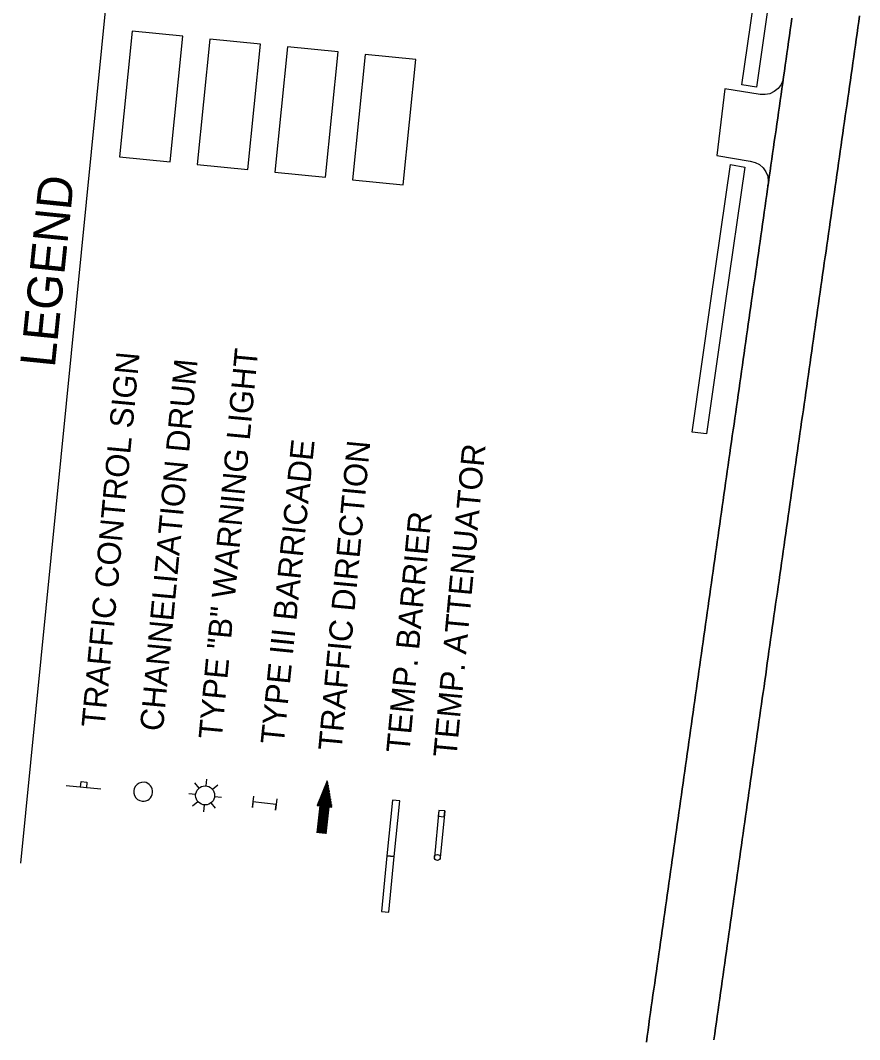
# Model space of a CAD drawing. Extents: x 1795987 to 1799700, y 243690 to 251545.
# Drawn here: x 1797261.2 to 1797542.5, y 247111.4 to 247453.1 of the extents above; entities that cross this region are included whole.
import ezdxf

# ---------------------------------------------------------------- set-up
doc = ezdxf.new("R2010")
doc.units = 0
for name, color, linetype in [('EP', 7, 'Continuous'), ('LEGEND', 7, 'Continuous'), ('Level 23', 7, 'Continuous'), ('Level 62', 7, 'Continuous')]:
    doc.layers.add(name, color=color, linetype=linetype)

# ---------------------------------------------------------------- blocks, each defined once
blk = doc.blocks.new('T21LR')
at = {"layer": 'Level 23'}
for p, q in [((0, 2), (31.5, 2)), ((0, -2), (31.5, -2))]:
    blk.add_line(p, q, dxfattribs=at)
blk.add_lwpolyline([(0, -2), (4, -2), (4, 2), (0, 2)], close=True, dxfattribs=at)
blk.add_circle((31.5, 0), 2, dxfattribs=at)

msp = doc.modelspace()

# ---------------------------------------------------------------- linework, layer by layer
at = {"layer": 'EP'}
for p, q in [((1797507.92, 247430.67), (1797502.98, 247431.42)), ((1797499.19, 247404.72), (1797504.07, 247403.85)), ((1797491.2, 247314.5), (1797486.32, 247315.04))]:
    msp.add_line(p, q, dxfattribs=at)
for points in [[(1797502.98, 247431.42), (1797509.89, 247479.28), (1797512.41, 247496.92), (1797513.21, 247499.92), (1797514.39, 247502.79), (1797515.55, 247504.9), (1797517.77, 247509.13), (1797519.86, 247513.31), (1797520.78, 247515.42), (1797521.93, 247518.67), (1797522.28, 247519.96), (1797522.83, 247522.6), (1797523.1, 247524.61), (1797523.26, 247527.63), (1797523.1, 247531.02), (1797522.82, 247533.27), (1797521.91, 247537.81), (1797521.35, 247540.15), (1797520.54, 247543.7), (1797520.12, 247547.31), (1797520.09, 247550.71), (1797523.74, 247576.05), (1797530.2, 247621.54), (1797536.99, 247668.47)], [(1797541.84, 247667.67), (1797535.11, 247620.83), (1797528.62, 247575.39), (1797524.96, 247549.93), (1797525.06, 247548.02), (1797525.55, 247543.91), (1797526.45, 247539.86), (1797526.65, 247538.96), (1797527.41, 247535.59), (1797527.98, 247531.38), (1797528.16, 247527.13), (1797526.97, 247518.48), (1797526.28, 247516.25), (1797524.64, 247511.95), (1797522.63, 247507.8), (1797522.17, 247506.93), (1797521.53, 247505.59), (1797517.43, 247496.48), (1797514.72, 247478.52), (1797507.92, 247430.67)], [(1797486.32, 247315.04), (1797492.66, 247359.05), (1797499.19, 247404.72)], [(1797504.07, 247403.85), (1797497.45, 247358.32), (1797491.2, 247314.5)]]:
    msp.add_lwpolyline(points, dxfattribs=at)
at = {"layer": 'LEGEND'}
for p, q in [((1797261.35, 247170.53), (1797308.29, 247644.28)), ((1797288.14, 247195.31), (1797276.49, 247196.46)), ((1797321.07, 247195.7), (1797319.61, 247197.49)), ((1797323.41, 247196.41), (1797323.64, 247198.71)), ((1797327.36, 247196.72), (1797325.57, 247195.26)), ((1797364.05, 247198.17), (1797360.6, 247189.86)), ((1797365.57, 247189.3), (1797364.05, 247198.17)), ((1797319.92, 247193.55), (1797317.62, 247193.78)), ((1797326.28, 247192.92), (1797328.58, 247192.69)), ((1797318.84, 247189.74), (1797320.63, 247191.21)), ((1797322.78, 247190.06), (1797322.55, 247187.76)), ((1797326.59, 247188.98), (1797325.12, 247190.76)), ((1797361.53, 247189.75), (1797360.52, 247180.73)), ((1797360.6, 247189.86), (1797361.53, 247189.75)), ((1797363.62, 247180.38), (1797364.63, 247189.4)), ((1797364.63, 247189.4), (1797365.57, 247189.3))]:
    msp.add_line(p, q, dxfattribs=at)
for points in [[(1797311.42, 247405.67), (1797315.58, 247447.74), (1797298.6, 247449.42), (1797294.43, 247407.35)], [(1797337.45, 247403.09), (1797341.62, 247445.16), (1797324.63, 247446.84), (1797320.46, 247404.77)], [(1797363.49, 247400.51), (1797367.66, 247442.58), (1797350.67, 247444.26), (1797346.5, 247402.19)], [(1797389.53, 247397.93), (1797393.69, 247440), (1797376.71, 247441.68), (1797372.54, 247399.61)], [(1797281.34, 247195.98), (1797281.54, 247197.92), (1797283.48, 247197.73), (1797283.28, 247195.79)], [(1797388.35, 247191.39), (1797385.87, 247191.64), (1797384.02, 247172.98), (1797386.51, 247172.73)], [(1797386.51, 247172.73), (1797384.02, 247172.98), (1797382.17, 247154.32), (1797384.66, 247154.07)]]:
    msp.add_lwpolyline(points, close=True, dxfattribs=at)
for points in [[(1797363.56, 247196.99), (1797361.71, 247180.59)], [(1797363.91, 247197.85), (1797361.97, 247180.56)], [(1797364.15, 247197.6), (1797362.23, 247180.53)], [(1797364.31, 247196.68), (1797362.49, 247180.5)], [(1797347.12, 247192.11), (1797346.67, 247188.24), (1797346.89, 247190.18), (1797339.14, 247191.08), (1797338.92, 247189.14), (1797339.37, 247193.01)], [(1797362.12, 247193.53), (1797360.68, 247180.71)], [(1797362.48, 247194.39), (1797360.94, 247180.68)], [(1797362.84, 247195.26), (1797361.2, 247180.65)], [(1797363.2, 247196.12), (1797361.45, 247180.62)], [(1797364.46, 247195.75), (1797362.75, 247180.48)], [(1797364.62, 247194.83), (1797363, 247180.45)], [(1797364.78, 247193.91), (1797363.26, 247180.42)], [(1797364.94, 247192.99), (1797363.52, 247180.39)], [(1797360.69, 247190.07), (1797360.66, 247189.85)], [(1797361.04, 247190.94), (1797360.92, 247189.82)], [(1797361.4, 247191.8), (1797361.18, 247189.79)], [(1797361.76, 247192.67), (1797361.44, 247189.76)], [(1797365.1, 247192.06), (1797364.79, 247189.38)], [(1797365.25, 247191.14), (1797365.05, 247189.35)], [(1797365.41, 247190.22), (1797365.31, 247189.33)]]:
    msp.add_lwpolyline(points, dxfattribs=at)
msp.add_circle((1797323.1, 247193.23), 3.19, dxfattribs=at)
for start, end in [(84.3414, 264.3414), (264.3414, 84.3414)]:
    msp.add_arc((1797302.33, 247194.48), 3.18, start, end, dxfattribs=at)
at = {"layer": 'Level 62'}
for points in [[(1797471, 247110.54), (1797471.28, 247112.51), (1797471.56, 247114.49), (1797471.84, 247116.46), (1797472.11, 247118.43), (1797472.39, 247120.41), (1797472.67, 247122.38), (1797472.95, 247124.35), (1797473.23, 247126.33), (1797473.51, 247128.3), (1797473.79, 247130.27), (1797474.07, 247132.25), (1797474.35, 247134.22), (1797474.63, 247136.19), (1797474.91, 247138.17), (1797475.19, 247140.14), (1797475.47, 247142.12), (1797475.75, 247144.09), (1797476.03, 247146.06), (1797476.31, 247148.04), (1797476.59, 247150.01), (1797476.87, 247151.98), (1797477.15, 247153.96), (1797477.42, 247155.93), (1797477.7, 247157.9), (1797477.98, 247159.88), (1797478.26, 247161.85), (1797478.54, 247163.83), (1797478.82, 247165.8), (1797479.1, 247167.77), (1797479.38, 247169.75), (1797479.66, 247171.72), (1797479.94, 247173.69), (1797480.22, 247175.67), (1797480.5, 247177.64), (1797480.78, 247179.61), (1797481.06, 247181.59), (1797481.34, 247183.56), (1797481.62, 247185.54), (1797481.9, 247187.51), (1797482.18, 247189.48), (1797482.46, 247191.46), (1797482.74, 247193.43), (1797483.01, 247195.4), (1797483.29, 247197.38), (1797483.57, 247199.35), (1797483.85, 247201.32), (1797484.13, 247203.3), (1797484.41, 247205.27), (1797484.69, 247207.25), (1797484.97, 247209.22), (1797485.25, 247211.19), (1797485.53, 247213.17), (1797485.81, 247215.14), (1797486.09, 247217.11), (1797486.37, 247219.09), (1797486.65, 247221.06), (1797486.93, 247223.03), (1797487.21, 247225.01), (1797487.49, 247226.98), (1797487.77, 247228.96), (1797488.05, 247230.93), (1797488.32, 247232.9), (1797488.6, 247234.88), (1797488.88, 247236.85), (1797489.16, 247238.82), (1797489.44, 247240.8), (1797489.72, 247242.77), (1797490, 247244.74), (1797490.28, 247246.72), (1797490.56, 247248.69), (1797490.84, 247250.67), (1797491.12, 247252.64), (1797491.4, 247254.61), (1797491.68, 247256.59), (1797491.96, 247258.56), (1797492.24, 247260.53), (1797492.52, 247262.51), (1797492.8, 247264.48), (1797493.08, 247266.45), (1797493.36, 247268.43), (1797493.63, 247270.4), (1797493.91, 247272.38), (1797494.19, 247274.35), (1797494.47, 247276.32), (1797494.76, 247278.3), (1797495.04, 247280.27), (1797495.32, 247282.24), (1797495.6, 247284.21), (1797495.88, 247286.19), (1797496.16, 247288.16), (1797496.44, 247290.13), (1797496.73, 247292.1), (1797497.01, 247294.08), (1797497.29, 247296.05), (1797497.57, 247298.02), (1797497.85, 247300), (1797498.13, 247301.97), (1797498.42, 247303.94), (1797498.7, 247305.91), (1797498.98, 247307.89), (1797499.26, 247309.86), (1797499.54, 247311.83), (1797499.82, 247313.8), (1797500.11, 247315.78), (1797500.39, 247317.75), (1797500.67, 247319.72), (1797500.95, 247321.7), (1797501.23, 247323.67), (1797501.51, 247325.64), (1797501.8, 247327.61), (1797502.08, 247329.59), (1797502.36, 247331.56), (1797502.64, 247333.53), (1797502.92, 247335.5), (1797503.2, 247337.48), (1797503.48, 247339.45), (1797503.77, 247341.42), (1797504.05, 247343.39), (1797504.33, 247345.37), (1797504.61, 247347.34), (1797504.89, 247349.31), (1797505.17, 247351.29), (1797505.46, 247353.26), (1797505.74, 247355.23), (1797506.02, 247357.2), (1797506.3, 247359.18), (1797506.58, 247361.15), (1797506.86, 247363.12), (1797507.15, 247365.09), (1797507.43, 247367.07), (1797507.71, 247369.04), (1797507.99, 247371.01), (1797508.27, 247372.99), (1797508.55, 247374.96), (1797508.84, 247376.93), (1797509.12, 247378.9), (1797509.4, 247380.88), (1797509.68, 247382.85), (1797509.96, 247384.82), (1797510.24, 247386.79), (1797510.52, 247388.77), (1797510.81, 247390.74), (1797511.09, 247392.71), (1797511.37, 247394.69), (1797511.65, 247396.66), (1797511.93, 247398.63), (1797512.21, 247400.6), (1797512.5, 247402.58), (1797512.78, 247404.55), (1797513.06, 247406.52), (1797513.34, 247408.49), (1797513.62, 247410.47), (1797513.9, 247412.44), (1797514.19, 247414.41), (1797514.47, 247416.39), (1797514.75, 247418.36), (1797515.03, 247420.33), (1797515.31, 247422.3), (1797515.59, 247424.28), (1797515.88, 247426.25), (1797516.16, 247428.22), (1797516.44, 247430.19), (1797516.72, 247432.17), (1797517, 247434.14), (1797517.28, 247436.11), (1797517.57, 247438.09), (1797517.85, 247440.06), (1797518.13, 247442.03), (1797518.41, 247444), (1797518.69, 247445.98), (1797518.97, 247447.95), (1797519.25, 247449.92), (1797519.54, 247451.89), (1797519.82, 247453.87)], [(1797519.82, 247453.87), (1797519.54, 247451.89), (1797519.25, 247449.92), (1797518.97, 247447.95), (1797518.69, 247445.98), (1797518.41, 247444), (1797518.13, 247442.03), (1797517.85, 247440.06), (1797517.57, 247438.09), (1797517.28, 247436.11), (1797517, 247434.14), (1797516.72, 247432.17), (1797516.44, 247430.19), (1797516.16, 247428.22), (1797515.88, 247426.25), (1797515.59, 247424.28), (1797515.31, 247422.3), (1797515.03, 247420.33), (1797514.75, 247418.36), (1797514.47, 247416.39), (1797514.19, 247414.41), (1797513.9, 247412.44), (1797513.62, 247410.47), (1797513.34, 247408.49), (1797513.06, 247406.52), (1797512.78, 247404.55), (1797512.5, 247402.58), (1797512.21, 247400.6), (1797511.93, 247398.63), (1797511.65, 247396.66), (1797511.37, 247394.69), (1797511.09, 247392.71), (1797510.81, 247390.74), (1797510.52, 247388.77), (1797510.24, 247386.79), (1797509.96, 247384.82), (1797509.68, 247382.85), (1797509.4, 247380.88), (1797509.12, 247378.9), (1797508.84, 247376.93), (1797508.55, 247374.96), (1797508.27, 247372.99), (1797507.99, 247371.01), (1797507.71, 247369.04), (1797507.43, 247367.07), (1797507.15, 247365.09), (1797506.86, 247363.12), (1797506.58, 247361.15), (1797506.3, 247359.18), (1797506.02, 247357.2), (1797505.74, 247355.23), (1797505.46, 247353.26), (1797505.17, 247351.29), (1797504.89, 247349.31), (1797504.61, 247347.34), (1797504.33, 247345.37), (1797504.05, 247343.39), (1797503.77, 247341.42), (1797503.48, 247339.45), (1797503.2, 247337.48), (1797502.92, 247335.5), (1797502.64, 247333.53), (1797502.36, 247331.56), (1797502.08, 247329.59), (1797501.8, 247327.61), (1797501.51, 247325.64), (1797501.23, 247323.67), (1797500.95, 247321.7), (1797500.67, 247319.72), (1797500.39, 247317.75), (1797500.11, 247315.78), (1797499.82, 247313.8), (1797499.54, 247311.83), (1797499.26, 247309.86), (1797498.98, 247307.89), (1797498.7, 247305.91), (1797498.42, 247303.94), (1797498.13, 247301.97), (1797497.85, 247300), (1797497.57, 247298.02), (1797497.29, 247296.05), (1797497.01, 247294.08), (1797496.73, 247292.1), (1797496.44, 247290.13), (1797496.16, 247288.16), (1797495.88, 247286.19), (1797495.6, 247284.21), (1797495.32, 247282.24), (1797495.04, 247280.27), (1797494.76, 247278.3), (1797494.47, 247276.32), (1797494.19, 247274.35), (1797493.91, 247272.38), (1797493.63, 247270.4), (1797493.36, 247268.43), (1797493.08, 247266.45), (1797492.8, 247264.48), (1797492.52, 247262.51), (1797492.24, 247260.53), (1797491.96, 247258.56), (1797491.68, 247256.59), (1797491.4, 247254.61), (1797491.12, 247252.64), (1797490.84, 247250.67), (1797490.56, 247248.69), (1797490.28, 247246.72), (1797490, 247244.74), (1797489.72, 247242.77), (1797489.44, 247240.8), (1797489.16, 247238.82), (1797488.88, 247236.85), (1797488.6, 247234.88), (1797488.32, 247232.9), (1797488.05, 247230.93), (1797487.77, 247228.96), (1797487.49, 247226.98), (1797487.21, 247225.01), (1797486.93, 247223.03), (1797486.65, 247221.06), (1797486.37, 247219.09), (1797486.09, 247217.11), (1797485.81, 247215.14), (1797485.53, 247213.17), (1797485.25, 247211.19), (1797484.97, 247209.22), (1797484.69, 247207.25), (1797484.41, 247205.27), (1797484.13, 247203.3), (1797483.85, 247201.32), (1797483.57, 247199.35), (1797483.29, 247197.38), (1797483.01, 247195.4), (1797482.74, 247193.43), (1797482.46, 247191.46), (1797482.18, 247189.48), (1797481.9, 247187.51), (1797481.62, 247185.54), (1797481.34, 247183.56), (1797481.06, 247181.59), (1797480.78, 247179.61), (1797480.5, 247177.64), (1797480.22, 247175.67), (1797479.94, 247173.69), (1797479.66, 247171.72), (1797479.38, 247169.75), (1797479.1, 247167.77), (1797478.82, 247165.8), (1797478.54, 247163.83), (1797478.26, 247161.85), (1797477.98, 247159.88), (1797477.7, 247157.9), (1797477.42, 247155.93), (1797477.15, 247153.96), (1797476.87, 247151.98), (1797476.59, 247150.01), (1797476.31, 247148.04), (1797476.03, 247146.06), (1797475.75, 247144.09), (1797475.47, 247142.12), (1797475.19, 247140.14), (1797474.91, 247138.17), (1797474.63, 247136.19), (1797474.35, 247134.22), (1797474.07, 247132.25), (1797473.79, 247130.27), (1797473.51, 247128.3), (1797473.23, 247126.33), (1797472.95, 247124.35), (1797472.67, 247122.38), (1797472.39, 247120.41), (1797472.11, 247118.43), (1797471.84, 247116.46), (1797471.56, 247114.49), (1797471.28, 247112.51), (1797471, 247110.54)], [(1797542.49, 247454.65), (1797542.21, 247452.67), (1797541.93, 247450.7), (1797541.65, 247448.73), (1797541.36, 247446.76), (1797541.08, 247444.78), (1797540.8, 247442.81), (1797540.52, 247440.84), (1797540.24, 247438.87), (1797539.96, 247436.89), (1797539.67, 247434.92), (1797539.39, 247432.95), (1797539.11, 247430.98), (1797538.83, 247429), (1797538.55, 247427.03), (1797538.27, 247425.06), (1797537.99, 247423.09), (1797537.7, 247421.11), (1797537.42, 247419.14), (1797537.14, 247417.17), (1797536.86, 247415.2), (1797536.58, 247413.22), (1797536.3, 247411.25), (1797536.01, 247409.28), (1797535.73, 247407.31), (1797535.45, 247405.33), (1797535.17, 247403.36), (1797534.89, 247401.39), (1797534.61, 247399.42), (1797534.32, 247397.44), (1797534.04, 247395.47), (1797533.76, 247393.5), (1797533.48, 247391.53), (1797533.2, 247389.56), (1797532.92, 247387.58), (1797532.64, 247385.61), (1797532.35, 247383.64), (1797532.07, 247381.67), (1797531.79, 247379.69), (1797531.51, 247377.72), (1797531.23, 247375.75), (1797530.95, 247373.78), (1797530.66, 247371.8), (1797530.38, 247369.83), (1797530.1, 247367.86), (1797529.82, 247365.89), (1797529.54, 247363.91), (1797529.26, 247361.94), (1797528.98, 247359.97), (1797528.69, 247358), (1797528.41, 247356.02), (1797528.13, 247354.05), (1797527.85, 247352.08), (1797527.57, 247350.11), (1797527.29, 247348.13), (1797527, 247346.16), (1797526.72, 247344.19), (1797526.44, 247342.22), (1797526.16, 247340.24), (1797525.88, 247338.27), (1797525.6, 247336.3), (1797525.31, 247334.33), (1797525.03, 247332.35), (1797524.75, 247330.38), (1797524.47, 247328.41), (1797524.19, 247326.44), (1797523.91, 247324.46), (1797523.63, 247322.49), (1797523.34, 247320.52), (1797523.06, 247318.55), (1797522.78, 247316.57), (1797522.5, 247314.6), (1797522.22, 247312.63), (1797521.94, 247310.66), (1797521.65, 247308.68), (1797521.37, 247306.71), (1797521.09, 247304.74), (1797520.81, 247302.77), (1797520.53, 247300.79), (1797520.25, 247298.82), (1797519.96, 247296.85), (1797519.68, 247294.88), (1797519.4, 247292.9), (1797519.12, 247290.93), (1797518.84, 247288.96), (1797518.56, 247286.99), (1797518.28, 247285.01), (1797517.99, 247283.04), (1797517.71, 247281.07), (1797517.43, 247279.1), (1797517.15, 247277.12), (1797516.87, 247275.15), (1797516.59, 247273.18), (1797516.31, 247271.21), (1797516.03, 247269.23), (1797515.75, 247267.26), (1797515.47, 247265.28), (1797515.19, 247263.31), (1797514.91, 247261.34), (1797514.63, 247259.36), (1797514.35, 247257.39), (1797514.07, 247255.41), (1797513.79, 247253.44), (1797513.51, 247251.47), (1797513.23, 247249.49), (1797512.95, 247247.52), (1797512.67, 247245.55), (1797512.39, 247243.57), (1797512.11, 247241.6), (1797511.83, 247239.62), (1797511.55, 247237.65), (1797511.28, 247235.68), (1797511, 247233.7), (1797510.72, 247231.73), (1797510.44, 247229.76), (1797510.16, 247227.78), (1797509.88, 247225.81), (1797509.6, 247223.83), (1797509.32, 247221.86), (1797509.04, 247219.89), (1797508.76, 247217.91), (1797508.48, 247215.94), (1797508.2, 247213.97), (1797507.92, 247211.99), (1797507.64, 247210.02), (1797507.36, 247208.04), (1797507.08, 247206.07), (1797506.8, 247204.1), (1797506.52, 247202.12), (1797506.24, 247200.15), (1797505.96, 247198.18), (1797505.69, 247196.2), (1797505.41, 247194.23), (1797505.13, 247192.25), (1797504.85, 247190.28), (1797504.57, 247188.31), (1797504.29, 247186.33), (1797504.01, 247184.36), (1797503.73, 247182.39), (1797503.45, 247180.41), (1797503.17, 247178.44), (1797502.89, 247176.46), (1797502.61, 247174.49), (1797502.33, 247172.52), (1797502.05, 247170.54), (1797501.77, 247168.57), (1797501.49, 247166.6), (1797501.21, 247164.62), (1797500.93, 247162.65), (1797500.65, 247160.67), (1797500.37, 247158.7), (1797500.1, 247156.73), (1797499.82, 247154.75), (1797499.54, 247152.78), (1797499.26, 247150.8), (1797498.98, 247148.83), (1797498.7, 247146.86), (1797498.42, 247144.88), (1797498.14, 247142.91), (1797497.86, 247140.94), (1797497.58, 247138.96), (1797497.3, 247136.99), (1797497.02, 247135.01), (1797496.74, 247133.04), (1797496.46, 247131.07), (1797496.18, 247129.09), (1797495.9, 247127.12), (1797495.62, 247125.15), (1797495.34, 247123.17), (1797495.06, 247121.2), (1797494.78, 247119.22), (1797494.51, 247117.25), (1797494.23, 247115.28), (1797493.95, 247113.3), (1797493.67, 247111.33)], [(1797493.67, 247111.33), (1797493.95, 247113.3), (1797494.23, 247115.28), (1797494.51, 247117.25), (1797494.78, 247119.22), (1797495.06, 247121.2), (1797495.34, 247123.17), (1797495.62, 247125.15), (1797495.9, 247127.12), (1797496.18, 247129.09), (1797496.46, 247131.07), (1797496.74, 247133.04), (1797497.02, 247135.01), (1797497.3, 247136.99), (1797497.58, 247138.96), (1797497.86, 247140.94), (1797498.14, 247142.91), (1797498.42, 247144.88), (1797498.7, 247146.86), (1797498.98, 247148.83), (1797499.26, 247150.8), (1797499.54, 247152.78), (1797499.82, 247154.75), (1797500.1, 247156.73), (1797500.37, 247158.7), (1797500.65, 247160.67), (1797500.93, 247162.65), (1797501.21, 247164.62), (1797501.49, 247166.6), (1797501.77, 247168.57), (1797502.05, 247170.54), (1797502.33, 247172.52), (1797502.61, 247174.49), (1797502.89, 247176.46), (1797503.17, 247178.44), (1797503.45, 247180.41), (1797503.73, 247182.39), (1797504.01, 247184.36), (1797504.29, 247186.33), (1797504.57, 247188.31), (1797504.85, 247190.28), (1797505.13, 247192.25), (1797505.41, 247194.23), (1797505.69, 247196.2), (1797505.96, 247198.18), (1797506.24, 247200.15), (1797506.52, 247202.12), (1797506.8, 247204.1), (1797507.08, 247206.07), (1797507.36, 247208.04), (1797507.64, 247210.02), (1797507.92, 247211.99), (1797508.2, 247213.97), (1797508.48, 247215.94), (1797508.76, 247217.91), (1797509.04, 247219.89), (1797509.32, 247221.86), (1797509.6, 247223.83), (1797509.88, 247225.81), (1797510.16, 247227.78), (1797510.44, 247229.76), (1797510.72, 247231.73), (1797511, 247233.7), (1797511.28, 247235.68), (1797511.55, 247237.65), (1797511.83, 247239.62), (1797512.11, 247241.6), (1797512.39, 247243.57), (1797512.67, 247245.55), (1797512.95, 247247.52), (1797513.23, 247249.49), (1797513.51, 247251.47), (1797513.79, 247253.44), (1797514.07, 247255.41), (1797514.35, 247257.39), (1797514.63, 247259.36), (1797514.91, 247261.34), (1797515.19, 247263.31), (1797515.47, 247265.28), (1797515.75, 247267.26), (1797516.03, 247269.23), (1797516.31, 247271.21), (1797516.59, 247273.18), (1797516.87, 247275.15), (1797517.15, 247277.12), (1797517.43, 247279.1), (1797517.71, 247281.07), (1797517.99, 247283.04), (1797518.28, 247285.01), (1797518.56, 247286.99), (1797518.84, 247288.96), (1797519.12, 247290.93), (1797519.4, 247292.9), (1797519.68, 247294.88), (1797519.96, 247296.85), (1797520.25, 247298.82), (1797520.53, 247300.79), (1797520.81, 247302.77), (1797521.09, 247304.74), (1797521.37, 247306.71), (1797521.65, 247308.68), (1797521.94, 247310.66), (1797522.22, 247312.63), (1797522.5, 247314.6), (1797522.78, 247316.57), (1797523.06, 247318.55), (1797523.34, 247320.52), (1797523.63, 247322.49), (1797523.91, 247324.46), (1797524.19, 247326.44), (1797524.47, 247328.41), (1797524.75, 247330.38), (1797525.03, 247332.35), (1797525.31, 247334.33), (1797525.6, 247336.3), (1797525.88, 247338.27), (1797526.16, 247340.24), (1797526.44, 247342.22), (1797526.72, 247344.19), (1797527, 247346.16), (1797527.29, 247348.13), (1797527.57, 247350.11), (1797527.85, 247352.08), (1797528.13, 247354.05), (1797528.41, 247356.02), (1797528.69, 247358), (1797528.98, 247359.97), (1797529.26, 247361.94), (1797529.54, 247363.91), (1797529.82, 247365.89), (1797530.1, 247367.86), (1797530.38, 247369.83), (1797530.66, 247371.8), (1797530.95, 247373.78), (1797531.23, 247375.75), (1797531.51, 247377.72), (1797531.79, 247379.69), (1797532.07, 247381.67), (1797532.35, 247383.64), (1797532.64, 247385.61), (1797532.92, 247387.58), (1797533.2, 247389.56), (1797533.48, 247391.53), (1797533.76, 247393.5), (1797534.04, 247395.47), (1797534.32, 247397.44), (1797534.61, 247399.42), (1797534.89, 247401.39), (1797535.17, 247403.36), (1797535.45, 247405.33), (1797535.73, 247407.31), (1797536.01, 247409.28), (1797536.3, 247411.25), (1797536.58, 247413.22), (1797536.86, 247415.2), (1797537.14, 247417.17), (1797537.42, 247419.14), (1797537.7, 247421.11), (1797537.99, 247423.09), (1797538.27, 247425.06), (1797538.55, 247427.03), (1797538.83, 247429), (1797539.11, 247430.98), (1797539.39, 247432.95), (1797539.67, 247434.92), (1797539.96, 247436.89), (1797540.24, 247438.87), (1797540.52, 247440.84), (1797540.8, 247442.81), (1797541.08, 247444.78), (1797541.36, 247446.76), (1797541.65, 247448.73), (1797541.93, 247450.7), (1797542.21, 247452.67), (1797542.49, 247454.65)], [(1797346.5, 247402.19), (1797363.49, 247400.51), (1797367.66, 247442.58), (1797350.67, 247444.26), (1797346.5, 247402.19)], [(1797516.85, 247433.11), (1797516.85, 247433.11), (1797516.19, 247431.59), (1797515.19, 247430.26), (1797513.9, 247429.22), (1797512.4, 247428.51), (1797510.78, 247428.18), (1797509.12, 247428.24), (1797497.35, 247430.15), (1797494.65, 247407.73), (1797505.83, 247405.84), (1797507.43, 247405.49), (1797508.89, 247404.75), (1797510.13, 247403.69), (1797511.08, 247402.36), (1797511.67, 247400.84), (1797511.88, 247399.22), (1797511.69, 247397.59), (1797511.78, 247397.58), (1797511.93, 247398.63), (1797512.21, 247400.6), (1797512.5, 247402.58), (1797512.78, 247404.55), (1797513.06, 247406.52), (1797513.34, 247408.49), (1797513.62, 247410.47), (1797513.9, 247412.44), (1797514.19, 247414.41), (1797514.47, 247416.39), (1797514.75, 247418.36), (1797515.03, 247420.33), (1797515.31, 247422.3), (1797515.59, 247424.28), (1797515.88, 247426.25), (1797516.16, 247428.22), (1797516.44, 247430.19), (1797516.72, 247432.17), (1797516.85, 247433.11)]]:
    msp.add_lwpolyline(points, dxfattribs=at)

# ---------------------------------------------------------------- block references
at = {"layer": 'LEGEND', "xscale": 0.5000000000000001, "yscale": 0.5000000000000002, "rotation": -95.50928026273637}
msp.add_blockref('T21LR', (1797402.45, 247188.12), dxfattribs=at)

# ---------------------------------------------------------------- texts
at = {"layer": 'LEGEND'}
for s, height, rotation, p in [('LEGEND', 11.7, 84.1754, (1797272.68, 247336.47)), ('TYPE "B" WARNING LIGHT', 7.7999, 84.6544, (1797328.64, 247211.85)), ('TRAFFIC CONTROL SIGN', 7.7999, 84.6544, (1797289.39, 247215.75)), ('CHANNELIZATION DRUM', 7.7999, 84.6544, (1797308.94, 247214.55)), ('TYPE III BARRICADE', 7.7999, 84.1754, (1797349.42, 247210.1)), ('TRAFFIC DIRECTION', 7.7999, 84.6544, (1797368.78, 247208.01)), ('TEMP. ATTENUATOR', 7.7999, 84.6544, (1797407.32, 247205.74)), ('TEMP. BARRIER', 7.7999, 84.6544, (1797391.55, 247207.25))]:
    msp.add_text(s, height=height, rotation=rotation, dxfattribs=at).set_placement(p)

doc.saveas('drawing.dxf')
